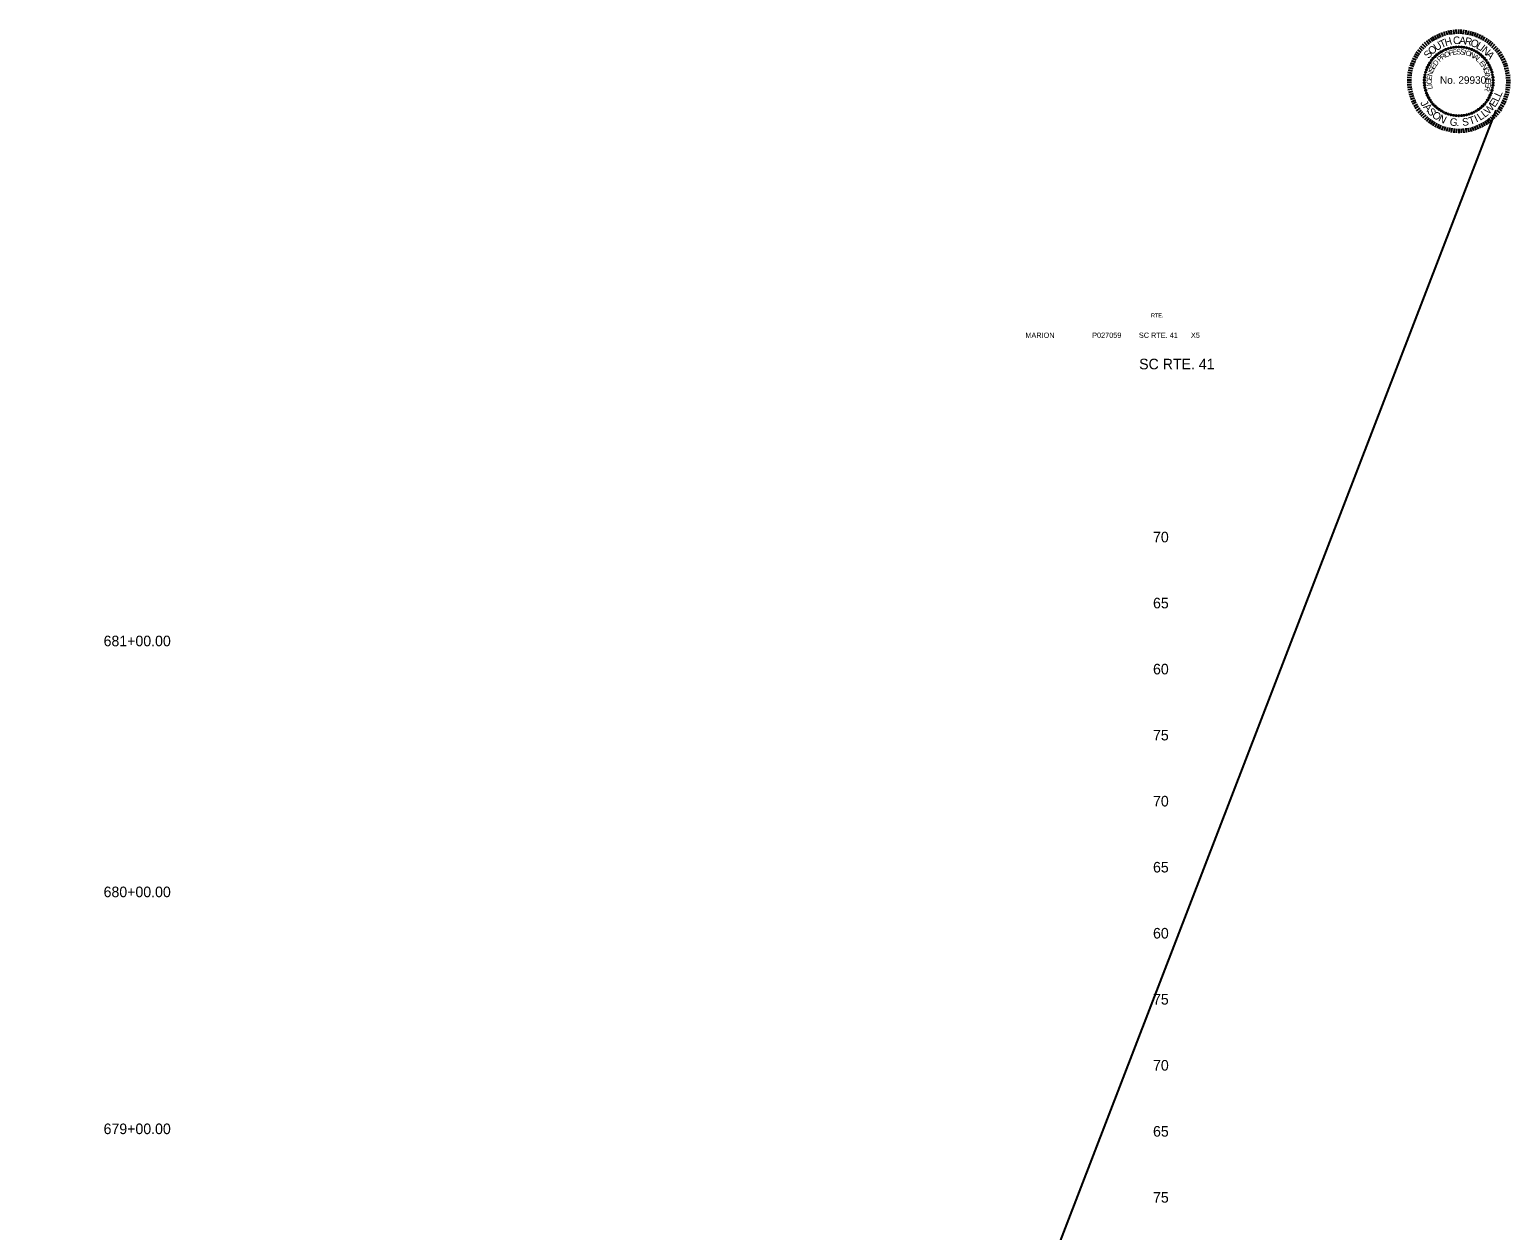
# Model space of a CAD drawing. Extents: x 952 to 1206, y 942 to 2399.
# Drawn here: x 1071.8 to 1184, y 1492.9 to 1583.8 of the extents above; entities that cross this region are included whole.
import ezdxf

# ---------------------------------------------------------------- set-up
doc = ezdxf.new("R2010")
doc.units = 0
for name, color, linetype in [('Default', 7, 'Continuous'), ('RD_SHT_TX', 7, 'Continuous'), ('RD_TX_PEShield', 7, 'Continuous'), ('RD_XS_TX_Elev_EX', 7, 'Continuous'), ('RD_XS_TX_Station', 7, 'Continuous')]:
    doc.layers.add(name, color=color, linetype=linetype)

# ---------------------------------------------------------------- blocks, each defined once
blk = doc.blocks.new('STILLWELL')
at = {"layer": 'RD_TX_PEShield'}
for p, q in [((-16.7, 30.8), (-18.2, 33.7)), ((-15.1, 31.6), (-16.5, 34.6)), ((-13.6, 32.3), (-14.8, 35.3)), ((-11.9, 32.9), (-13, 36)), ((-10.3, 33.4), (-11.2, 36.6)), ((-8.6, 33.9), (-9.4, 37.1)), ((-6.9, 34.3), (-7.5, 37.5)), ((-5.2, 34.6), (-5.7, 37.8)), ((-3.5, 34.8), (-3.8, 38)), ((-1.8, 34.9), (-1.9, 38.2)), ((0, 34.9), (0, 38.2)), ((1.7, 34.9), (1.9, 38.2)), ((3.4, 34.8), (3.7, 38)), ((5.2, 34.6), (5.6, 37.8)), ((6.9, 34.3), (7.5, 37.5)), ((8.6, 33.9), (9.3, 37.1)), ((10.2, 33.4), (11.2, 36.6)), ((11.9, 32.9), (13, 36)), ((13.5, 32.3), (14.7, 35.3)), ((15.1, 31.6), (16.5, 34.6)), ((16.6, 30.8), (18.2, 33.7)), ((-28.5, 20.9), (-31.1, 22.8)), ((-27.4, 22.2), (-29.9, 24.3)), ((-26.3, 23.5), (-28.7, 25.7)), ((-25.1, 24.7), (-27.4, 27.1)), ((-23.8, 25.9), (-26, 28.4)), ((-22.5, 27), (-24.5, 29.6)), ((-21.1, 28.1), (-23, 30.7)), ((-19.7, 29.1), (-21.5, 31.8)), ((-18.2, 30), (-19.9, 32.8)), ((18.2, 30), (19.8, 32.8)), ((19.6, 29.1), (21.4, 31.8)), ((21.1, 28.1), (23, 30.7)), ((22.4, 27), (24.5, 29.6)), ((23.8, 25.9), (25.9, 28.4)), ((25, 24.7), (27.3, 27.1)), ((26.2, 23.5), (28.6, 25.7)), ((27.4, 22.2), (29.9, 24.3)), ((28.5, 20.9), (31.1, 22.8)), ((-33.6, 11.8), (-36.6, 12.9)), ((-32.9, 13.4), (-35.9, 14.7)), ((-32.2, 15), (-35.1, 16.4)), ((-31.4, 16.5), (-34.2, 18.1)), ((-30.5, 18), (-33.3, 19.7)), ((-29.5, 19.4), (-32.2, 21.3)), ((29.5, 19.4), (32.2, 21.3)), ((30.4, 18), (33.2, 19.7)), ((31.3, 16.5), (34.2, 18.1)), ((32.1, 15), (35.1, 16.4)), ((32.9, 13.4), (35.9, 14.7)), ((33.5, 11.8), (36.6, 12.9)), ((-35.9, -0.1), (-39.2, 0)), ((-35.8, 1.7), (-39.1, 1.9)), ((-35.6, 3.4), (-38.9, 3.8)), ((-35.4, 5.1), (-38.6, 5.7)), ((-35.1, 6.8), (-38.2, 7.5)), ((-34.6, 8.5), (-37.8, 9.4)), ((-34.1, 10.2), (-37.2, 11.2)), ((34.1, 10.2), (37.2, 11.2)), ((34.6, 8.5), (37.7, 9.4)), ((35, 6.8), (38.2, 7.5)), ((35.3, 5.1), (38.5, 5.7)), ((35.6, 3.4), (38.8, 3.8)), ((35.7, 1.7), (39, 1.9)), ((35.8, -0.1), (39.1, 0)), ((-35.9, -1.8), (-39.2, -1.9)), ((-35.8, -3.5), (-39.1, -3.8)), ((-35.6, -5.3), (-38.9, -5.6)), ((-35.4, -7), (-38.6, -7.5)), ((-35.1, -8.7), (-38.2, -9.4)), ((-34.6, -10.4), (-37.8, -11.2)), ((34.6, -10.4), (37.7, -11.2)), ((35, -8.7), (38.2, -9.4)), ((35.3, -7), (38.5, -7.5)), ((35.6, -5.3), (38.8, -5.6)), ((35.7, -3.5), (39, -3.8)), ((35.8, -1.8), (39.1, -1.9)), ((-34.1, -12), (-37.2, -13)), ((-33.6, -13.6), (-36.6, -14.8)), ((-32.9, -15.3), (-35.9, -16.6)), ((-32.2, -16.8), (-35.1, -18.3)), ((-31.4, -18.4), (-34.2, -19.9)), ((-30.5, -19.9), (-33.3, -21.6)), ((-29.5, -21.3), (-32.2, -23.2)), ((29.5, -21.3), (32.2, -23.2)), ((30.4, -19.9), (33.2, -21.6)), ((31.3, -18.4), (34.2, -19.9)), ((32.1, -16.8), (35.1, -18.3)), ((32.9, -15.3), (35.9, -16.6)), ((33.5, -13.6), (36.6, -14.8)), ((34.1, -12), (37.2, -13)), ((-28.5, -22.7), (-31.1, -24.7)), ((-27.4, -24.1), (-29.9, -26.2)), ((-26.3, -25.4), (-28.7, -27.6)), ((-25.1, -26.6), (-27.4, -28.9)), ((-23.8, -27.8), (-26, -30.2)), ((-22.5, -28.9), (-24.5, -31.4)), ((-21.1, -29.9), (-23, -32.6)), ((-19.7, -30.9), (-21.5, -33.7)), ((-18.2, -31.8), (-19.9, -34.7)), ((-16.7, -32.7), (-18.2, -35.6)), ((-15.1, -33.5), (-16.5, -36.4)), ((15.1, -33.5), (16.5, -36.4)), ((16.6, -32.7), (18.2, -35.6)), ((18.2, -31.8), (19.8, -34.7)), ((19.6, -30.9), (21.4, -33.7)), ((21.1, -29.9), (23, -32.6)), ((22.4, -28.9), (24.5, -31.4)), ((23.8, -27.8), (25.9, -30.2)), ((25, -26.6), (27.3, -28.9)), ((26.2, -25.4), (28.6, -27.6)), ((27.4, -24.1), (29.9, -26.2)), ((28.5, -22.7), (31.1, -24.7)), ((-13.6, -34.1), (-14.8, -37.2)), ((-11.9, -34.8), (-13, -37.8)), ((-10.3, -35.3), (-11.2, -38.4)), ((-8.6, -35.8), (-9.4, -38.9)), ((-6.9, -36.1), (-7.5, -39.3)), ((-5.2, -36.4), (-5.7, -39.7)), ((-3.5, -36.6), (-3.8, -39.9)), ((-1.8, -36.8), (-1.9, -40)), ((0, -36.8), (0, -40.1)), ((1.7, -36.8), (1.9, -40)), ((3.4, -36.6), (3.7, -39.9)), ((5.2, -36.4), (5.6, -39.7)), ((6.9, -36.1), (7.5, -39.3)), ((8.6, -35.8), (9.3, -38.9)), ((10.2, -35.3), (11.2, -38.4)), ((11.9, -34.8), (13, -37.8)), ((13.5, -34.1), (14.7, -37.2))]:
    blk.add_line(p, q, dxfattribs=at)
for centre in [(-11.6, 22.4), (-9.8, 23.2), (-7.9, 23.9), (-6, 24.4), (-4, 24.8), (-2, 25), (0, 25.1), (2, 25), (3.9, 24.8), (5.9, 24.4), (7.8, 23.9), (9.7, 23.2), (11.5, 22.4), (-22.9, 11.5), (-21.9, 13.2), (-20.7, 14.9), (-19.5, 16.4), (-18.1, 17.8), (-16.6, 19.2), (-15, 20.4), (-13.3, 21.5), (13.3, 21.5), (15, 20.4), (16.5, 19.2), (18, 17.8), (19.4, 16.4), (20.7, 14.9), (21.8, 13.2), (22.9, 11.5), (-26.1, 0.1), (-25.9, 2.1), (-25.6, 4), (-25.1, 6), (-24.5, 7.9), (-23.8, 9.7), (23.7, 9.7), (24.5, 7.9), (25.1, 6), (25.5, 4), (25.8, 2.1), (26, 0.1), (-26.1, -1.9), (-25.9, -3.9), (-25.6, -5.9), (-25.1, -7.8), (-24.5, -9.7), (-23.8, -11.6), (23.7, -11.6), (24.5, -9.7), (25.1, -7.8), (25.5, -5.9), (25.8, -3.9), (26, -1.9), (-22.9, -13.4), (-21.9, -15.1), (-20.7, -16.7), (-19.5, -18.3), (-18.1, -19.7), (-16.6, -21), (-15, -22.2), (15, -22.2), (16.5, -21), (18, -19.7), (19.4, -18.3), (20.7, -16.7), (21.8, -15.1), (22.9, -13.4), (-13.3, -23.3), (-11.6, -24.3), (-9.8, -25.1), (-7.9, -25.8), (-6, -26.3), (-4, -26.7), (-2, -26.9), (0, -27), (2, -26.9), (3.9, -26.7), (5.9, -26.3), (7.8, -25.8), (9.7, -25.1), (11.5, -24.3), (13.3, -23.3)]:
    blk.add_circle(centre, 0.49, dxfattribs=at)
for s, height, rotation, p in [('S', 5.68, 49.6435, (-22.9, 15.8)), ('O', 5.68, 41.5972, (-20.4, 18.8)), ('U', 5.68, 32.2152, (-16.9, 21.8)), ('T', 5.68, 23.5044, (-13.2, 24.1)), ('H', 5.68, 16.1357, (-9.9, 25.6)), ('F', 3.92, 15.9995, (-7.1, 18.3)), ('E', 3.92, 8.9511, (-4.7, 19)), ('C', 5.68, 4.076, (-4.2, 27.1)), ('S', 3.92, 1.2546, (-1.9, 19.4)), ('A', 5.68, 355.3651, (0.1, 27.4)), ('S', 3.92, 353.558, (0.8, 19.5)), ('I', 3.92, 345.8615, (3.5, 19.2)), ('R', 5.68, 347.3188, (4.1, 27.1)), ('O', 5.68, 338.6079, (8.3, 26.2)), ('L', 5.68, 329.226, (12.6, 24.4)), ('I', 5.68, 322.5218, (15.5, 22.8)), ('N', 5.68, 319.1729, (16.8, 21.8)), ('E', 3.92, 60.2341, (-18.5, 7.9)), ('D', 3.92, 52.5376, (-17.1, 10.3)), ('P', 3.92, 41.0022, (-14.5, 13.5)), ('R', 3.92, 33.3057, (-12.5, 15.3)), ('O', 3.92, 24.9735, (-10, 16.9)), ('O', 3.92, 342.6583, (4.7, 19)), ('N', 3.92, 333.6842, (7.7, 18)), ('A', 3.92, 325.3521, (10.4, 16.7)), ('L', 3.92, 317.6555, (12.6, 15.1)), ('E', 3.92, 308.0396, (15.1, 12.8)), ('N', 3.92, 300.343, (16.8, 10.6)), ('A', 5.68, 310.4621, (20.1, 19)), ('C', 3.92, 92.2915, (-20.4, -3.2)), ('E', 3.92, 83.9594, (-20.5, -0.2)), ('N', 3.92, 76.2628, (-20.2, 2.5)), ('S', 3.92, 67.9307, (-19.5, 5.4)), ('G', 3.92, 292.0109, (18.3, 8.1)), ('I', 3.92, 283.0368, (19.5, 5.1)), ('N', 3.92, 279.8336, (19.8, 4)), ('E', 3.92, 271.5014, (20.3, 1.1)), ('I', 3.92, 95.4947, (-20.2, -4.3)), ('L', 3.92, 101.9075, (-19.7, -6.6)), ('R', 3.92, 256.1083, (20.1, -4.4)), ('E', 3.92, 263.8049, (20.4, -1.7)), ('L', 5.68, 65.098, (31.6, -13.3)), ('J', 5.68, 299.033, (-29.4, -17.3)), ('A', 5.68, 310.5887, (-27.2, -20.6)), ('S', 5.68, 310.5887, (-24.3, -24)), ('W', 5.68, 47.0518, (22.6, -26.4)), ('E', 5.68, 56.4327, (27.3, -21.1)), ('L', 5.68, 65.098, (30, -16.9)), ('O', 5.68, 321.0072, (-20.8, -27.4)), ('N', 5.68, 333.4326, (-16, -30.8)), ('G', 5.68, 352.2045, (-7.2, -34.2)), ('S', 5.68, 8.0826, (2.9, -34.8)), ('T', 5.68, 18.9019, (8.5, -33.9)), ('I', 5.68, 25.3991, (13.3, -32.2)), ('L', 5.68, 34.0644, (16.2, -30.9)), ('L', 5.68, 37.6708, (19.6, -28.7)), ('.', 5.68, 0.8698, (-1.8, -34.9))]:
    blk.add_text(s, height=height, rotation=rotation, dxfattribs=at).set_placement(p)
blk.add_text('No. 29930', height=5.68, dxfattribs=at).set_placement((-14.3, -2.8))

msp = doc.modelspace()

# ---------------------------------------------------------------- linework, layer by layer
at = {"layer": 'RD_SHT_TX'}
msp.add_line((951.99, 979.01), (1182.92, 1577.73), dxfattribs=at)

# ---------------------------------------------------------------- block references
at = {"layer": 'Default', "xscale": 0.1, "yscale": 0.10000000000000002}
msp.add_blockref('STILLWELL', (1180.08, 1580), dxfattribs=at)

# ---------------------------------------------------------------- texts
at = {"layer": 'RD_SHT_TX'}
for s, height, p in [('RTE.', 0.3, (1156.77, 1562.03)), ('MARION', 0.4, (1147.25, 1560.48)), ('P027059', 0.4, (1152.31, 1560.48)), ('SC RTE. 41', 0.4, (1155.85, 1560.48)), ('X5', 0.4, (1159.79, 1560.48)), ('SC RTE. 41', 0.8, (1155.87, 1558.1))]:
    msp.add_text(s, height=height, dxfattribs=at).set_placement(p)
at = {"layer": 'RD_XS_TX_Elev_EX'}
for s, p in [('70', (1156.92, 1545)), ('65', (1156.92, 1540)), ('60', (1156.92, 1535)), ('75', (1156.92, 1530)), ('70', (1156.92, 1525)), ('65', (1156.92, 1520)), ('60', (1156.92, 1515)), ('75', (1156.92, 1510)), ('70', (1156.92, 1505)), ('65', (1156.92, 1500)), ('75', (1156.92, 1495))]:
    msp.add_text(s, height=0.8, dxfattribs=at).set_placement(p)
at = {"layer": 'RD_XS_TX_Station'}
for s, p in [('681+00.00', (1077.44, 1537.13)), ('680+00.00', (1077.44, 1518.13)), ('679+00.00', (1077.44, 1500.19))]:
    msp.add_text(s, height=0.8, dxfattribs=at).set_placement(p)

doc.saveas('drawing.dxf')
